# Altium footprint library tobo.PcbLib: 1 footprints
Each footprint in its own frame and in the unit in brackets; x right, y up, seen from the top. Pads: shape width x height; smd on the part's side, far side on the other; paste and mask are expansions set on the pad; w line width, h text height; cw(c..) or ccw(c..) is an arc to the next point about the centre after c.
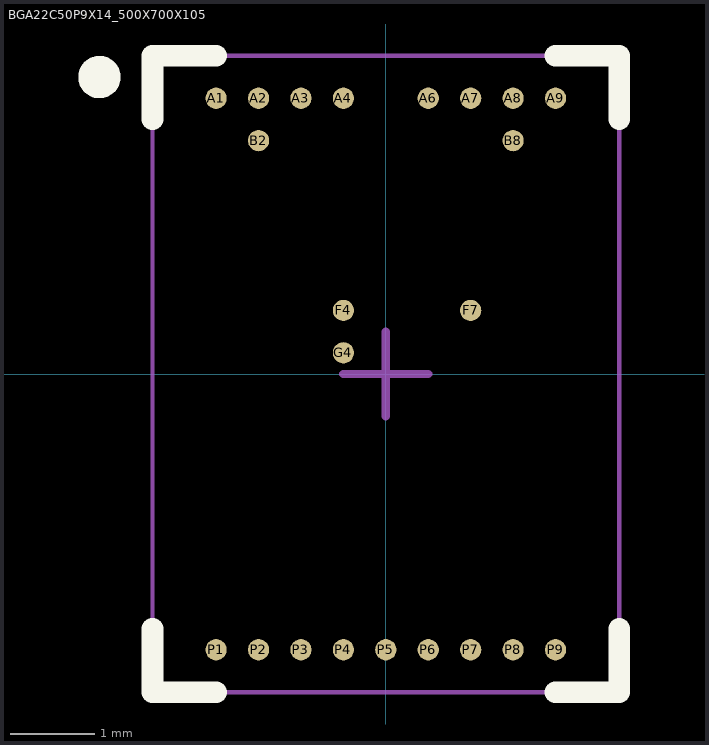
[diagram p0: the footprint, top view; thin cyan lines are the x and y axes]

## BGA22C50P9X14_500X700X105 [mm] "BGA, 22-Leads, Body 5.00x7.00mmx1.05mm, Pitch 0.50mm"
height 1.05
pads (22):
  round 0.25 smd: A1(-2,3.25) A2(-1.5,3.25) A3(-1,3.25) A4(-0.5,3.25) A6(0.5,3.25) A7(1,3.25) A8(1.5,3.25) A9(2,3.25) B2(-1.5,2.75) B8(1.5,2.75) F4(-0.5,0.75) F7(1,0.75) G4(-0.5,0.25) P1(-2,-3.25) P2(-1.5,-3.25) P3(-1,-3.25) P4(-0.5,-3.25) P5(0,-3.25) P6(0.5,-3.25) P7(1,-3.25) P8(1.5,-3.25) P9(2,-3.25)
Top Overlay:
  circle w0.25: c-3.375,3.5 r0.125
  lines w0.254: -2.75,-3 -2.75,-3.75 -2,-3.75 ; -2.75,3 -2.75,3.75 -2,3.75 ; 2,-3.75 2.75,-3.75 2.75,-3 ; 2,3.75 2.75,3.75 2.75,3
Mechanical 15:
  lines w0.05: -2.75,-3.75 2.75,-3.75 2.75,3.75 -2.75,3.75 -2.75,-3.75
  lines w0.1: -0.5,0 0.5,0 ; 0,-0.5 0,0.5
